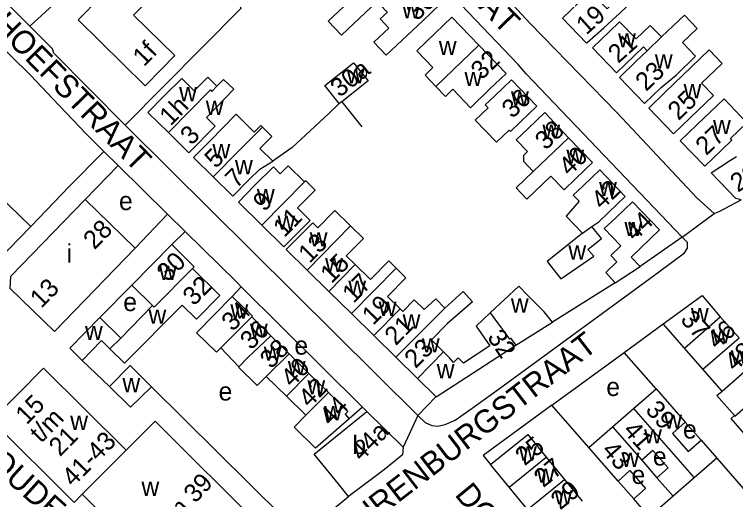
# Model space of a CAD drawing. Extents: x 161775 to 163181, y 382878 to 383925.
# Drawn here: x 162089.5 to 162245.9, y 383284.1 to 383389.4 of the extents above; entities that cross this region are included whole.
import ezdxf

# ---------------------------------------------------------------- set-up
doc = ezdxf.new("R2010")
doc.units = 0
for name, color, linetype in [('BLT_Basislijn', 7, 'Continuous'), ('BLT_Bebouwing', 7, 'Continuous'), ('BLT_Centroide', 7, 'Continuous'), ('BLT_Huisnummer', 7, 'Continuous'), ('BLT_Huisnummer_ tussenligend', 7, 'Continuous'), ('BLT_Huisnummer_reeks', 7, 'Continuous'), ('BLT_Onderverdeling_panden', 7, 'Continuous'), ('BLT_Straatnaam', 7, 'Continuous'), ('BLT_Vlakafsluiter', 7, 'Continuous')]:
    doc.layers.add(name, color=color, linetype=linetype)

msp = doc.modelspace()

# ---------------------------------------------------------------- linework, layer by layer
at = {"layer": 'BLT_Basislijn'}
for p, q in [((162092.87, 383386.85), (162105.88, 383398.85)), ((162160.52, 383370.45), (162164.88, 383365.03)), ((162101.31, 383351.92), (162108.95, 383359.68)), ((162112.07, 383356.6), (162108.95, 383359.68)), ((162112.07, 383356.6), (162104.91, 383349.23)), ((162122.75, 383346.08), (162112.07, 383356.6)), ((162115.77, 383338.71), (162122.75, 383346.08)), ((162126.57, 383342.32), (162122.75, 383346.08)), ((162123.66, 383339.48), (162126.57, 383342.32)), ((162234.37, 383341.1), (162225.23, 383334.73)), ((162108.07, 383323.63), (162115.01, 383330.69)), ((162219.85, 383331.17), (162206.25, 383322.64)), ((162136.8, 383328.2), (162138.75, 383330.31)), ((162221.8, 383316.06), (162230.27, 383322.28)), ((162206.1, 383304.59), (162221.8, 383316.06)), ((162228.69, 383308.2), (162221.8, 383316.06)), ((162104.22, 383314.35), (162110.16, 383308.68)), ((162119.27, 383308.6), (162151.77, 383276.48)), ((162177.06, 383302.39), (162180.93, 383306.42)), ((162165.07, 383304.18), (162166, 383303.24)), ((162214.1, 383295.44), (162206.1, 383304.59)), ((162238.47, 383297.02), (162235.04, 383300.94)), ((162223.85, 383284.29), (162220.45, 383288.17)), ((162151.77, 383276.48), (162162.02, 383284.83))]:
    msp.add_line(p, q, dxfattribs=at)
for points in [[(162125.25, 383476.9), (162123.02, 383475.95), (162121.82, 383474.13), (162121.64, 383471.58), (162122.43, 383469.75), (162125.33, 383466.48), (162163.61, 383428.2), (162170.77, 383419.99), (162181.31, 383409.13), (162201.49, 383387.36), (162220.16, 383368.12), (162237.6, 383349.53), (162241.27, 383346.24)], [(162234.37, 383341.1), (162200.53, 383376.54), (162198.79, 383378.55), (162180.32, 383397.96), (162171.16, 383407.28), (162152.54, 383427.04), (162145.46, 383434.09), (162144.51, 383435.3), (162141.14, 383438.66), (162128.28, 383452.45), (162114.65, 383465.76), (162108.97, 383469.83), (162104.5, 383472.05), (162097.57, 383474.16), (162097.57, 383474.32), (162092.85, 383474.91), (162089.56, 383474.77), (162025.83, 383467.96), (162025.67, 383467.75)], [(162114.43, 383407.55), (162118.99, 383411.97), (162119.75, 383411.23), (162136.39, 383393.66), (162138.37, 383391.5), (162138.68, 383390.7), (162113.58, 383365.34)], [(162092.87, 383386.85), (162075.69, 383403.95), (162072.1, 383408.19)], [(162036.52, 383357.08), (162059.8, 383379.79), (162066.65, 383386.36), (162068.12, 383387.55), (162074.17, 383393.72), (162075.21, 383393.82), (162093.13, 383376.16), (162097.9, 383371.1)], [(162113.58, 383365.34), (162098.09, 383380.96), (162097.78, 383381.95), (162093.25, 383386.47), (162092.87, 383386.85)], [(162108.95, 383359.68), (162105.09, 383363.48), (162097.9, 383371.1)], [(162160.01, 383370.04), (162157.65, 383367.84), (162149.81, 383360.51), (162145.58, 383357.59)], [(162113.58, 383365.34), (162113.98, 383364.93), (162177.06, 383302.39)], [(162093.09, 383343.41), (162099.88, 383350.45), (162101.31, 383351.92)], [(162241.27, 383346.24), (162242.36, 383346.62), (162247.15, 383349.17)], [(162138.75, 383330.31), (162137.68, 383331.37), (162126.57, 383342.32)], [(162177.06, 383302.39), (162178.64, 383300.88), (162180.1, 383300.19), (162181.38, 383300.08), (162182.96, 383300.43), (162185.1, 383301.34), (162189.29, 383304.3), (162194.72, 383308.27), (162223.02, 383328.96), (162229.49, 383333.71), (162234.9, 383337.68), (162235.51, 383338.68), (162235.51, 383339.94), (162234.37, 383341.1)], [(162138.75, 383330.31), (162165.07, 383304.18)], [(162165.07, 383304.18), (162162.15, 383301.66)], [(162206.1, 383304.59), (162191.24, 383293.73), (162192.82, 383291.78)], [(162241.86, 383293.15), (162278.02, 383251.56)]]:
    msp.add_lwpolyline(points, dxfattribs=at)
at = {"layer": 'BLT_Bebouwing'}
for p, q in [((162214.91, 383382.14), (162220.11, 383376.72)), ((162160.52, 383370.45), (162160.01, 383370.04)), ((162227.11, 383369.06), (162232.46, 383363.48)), ((162233.96, 383361.97), (162239.26, 383356.45)), ((162081.91, 383354.21), (162093.09, 383343.41)), ((162104.91, 383349.23), (162115.77, 383338.71)), ((162093.09, 383343.41), (162085.05, 383335.1)), ((162214.8, 383343.37), (162216.26, 383344.39)), ((162115.77, 383338.71), (162098.23, 383320.61)), ((162123.66, 383339.48), (162115.01, 383330.69)), ((162153.02, 383333.95), (162157.75, 383329.3)), ((162219.85, 383331.17), (162225.23, 383334.73)), ((162115.01, 383330.69), (162119.51, 383326.24)), ((162157.75, 383329.3), (162162.65, 383324.49)), ((162129.05, 383320.35), (162136.8, 383328.2)), ((162119.51, 383326.24), (162112.59, 383319.19)), ((162162.65, 383324.49), (162167.52, 383319.71)), ((162112.59, 383319.19), (162108.07, 383323.63)), ((162141.01, 383323.76), (162145.13, 383319.7)), ((162198.29, 383317.65), (162206.25, 383322.64)), ((162145.13, 383319.7), (162149.11, 383315.78)), ((162167.52, 383319.71), (162172.3, 383315.02)), ((162138.25, 383312.96), (162134.3, 383317.03)), ((162149.11, 383315.78), (162153.43, 383311.52)), ((162172.3, 383315.02), (162176.96, 383310.44)), ((162148.54, 383306.55), (162144.15, 383310.88)), ((162153.43, 383311.52), (162157.63, 383307.38)), ((162228.69, 383308.2), (162235.04, 383300.94)), ((162152.73, 383302.42), (162148.54, 383306.55)), ((162192.82, 383291.78), (162200.92, 383298.24)), ((162200.92, 383298.24), (162204.89, 383293.35)), ((162238.47, 383297.02), (162241.86, 383293.15)), ((162220.45, 383288.17), (162214.1, 383295.44)), ((162204.89, 383293.35), (162208.83, 383288.49)), ((162196.86, 383286.82), (162192.82, 383291.78)), ((162225.58, 383292.66), (162228.88, 383288.89)), ((162208.83, 383288.49), (162212.67, 383283.77)), ((162200.8, 383281.97), (162196.86, 383286.82)), ((162227.26, 383280.38), (162223.85, 383284.29))]:
    msp.add_line(p, q, dxfattribs=at)
for points in [[(162121.43, 383377.49), (162117.92, 383373.92), (162103.35, 383388.24), (162108.24, 383393.22), (162107.37, 383394.08), (162110.9, 383397.66), (162114.39, 383401.21), (162115.42, 383400.2), (162120.29, 383405.15), (162126.89, 383398.67), (162121.51, 383393.18), (162120.38, 383394.3), (162115.4, 383389.24), (162124.34, 383380.46), (162121.43, 383377.49)], [(162176.95, 383396.62), (162172.09, 383401.7), (162168.48, 383398.24), (162157.57, 383387.97), (162160.49, 383384.91), (162168.2, 383392.17), (162170.15, 383390.12)], [(162213.78, 383383.32), (162217.34, 383386.51), (162220.95, 383389.74), (162227.56, 383396.09), (162224.76, 383399), (162218.76, 383393.24), (162219.75, 383392.2), (162218.08, 383390.6), (162214.46, 383394.37), (162212.03, 383392.04), (162208.42, 383388.58)], [(162170.15, 383390.12), (162170.41, 383389.84), (162168.89, 383388.41), (162170.72, 383386.44), (162167.47, 383383.37), (162170.18, 383380.53), (162178.2, 383388.09), (162181.81, 383391.54), (162176.95, 383396.62)], [(162190.27, 383382.7), (162184.38, 383388.79), (162180.77, 383385.34), (162176.8, 383381.53), (162180.32, 383377.86), (162178.6, 383376.22), (162180.94, 383373.78)], [(162208.42, 383388.58), (162213.61, 383383.17), (162213.78, 383383.32)], [(162226.17, 383370.05), (162229.79, 383373.52), (162233.15, 383376.32), (162237.27, 383380.31), (162234.42, 383383.34), (162237.59, 383386.32), (162234.85, 383389.24), (162231.19, 383385.8), (162229.86, 383384.51)], [(162229.86, 383384.51), (162227.43, 383387.03), (162224.36, 383384.08), (162220.8, 383387.8), (162218.51, 383385.6), (162214.91, 383382.14)], [(162180.94, 383373.78), (162183.02, 383371.61), (162184.64, 383373.16), (162188.49, 383369.15), (162192.49, 383373.1), (162196.18, 383376.57), (162190.27, 383382.7)], [(162220.11, 383376.72), (162226.01, 383382.37), (162226.75, 383381.49)], [(162226.75, 383381.49), (162224.35, 383379.18), (162220.91, 383375.88)], [(162232.46, 383363.48), (162236.07, 383366.95), (162241.18, 383371.78), (162238.57, 383374.5), (162243.02, 383378.77), (162240.22, 383381.68), (162230.71, 383372.53), (162227.11, 383369.06)], [(162160.01, 383370.04), (162156.88, 383373.99), (162163.1, 383378.92), (162166.23, 383374.98), (162160.52, 383370.45)], [(162133.46, 383373.82), (162131.46, 383375.79), (162128.54, 383372.84), (162125.83, 383375.51), (162122.01, 383371.71), (162118.49, 383368.15), (162122.93, 383363.77)], [(162122.93, 383363.77), (162127.36, 383359.4), (162133.07, 383365.19), (162131.19, 383367.01), (162137.14, 383373.19), (162134.88, 383375.26), (162133.46, 383373.82)], [(162197.14, 383364.02), (162199.24, 383366.01), (162202.85, 383369.47), (162197.34, 383375.23), (162193.73, 383371.77), (162191.63, 383369.79), (162192.26, 383369.11), (162189.5, 383366.47), (162194.12, 383361.65), (162196.88, 383364.29), (162197.14, 383364.02)], [(162220.91, 383375.88), (162220.74, 383375.72), (162226.17, 383370.05)], [(162239.26, 383356.45), (162242.87, 383359.92), (162245.17, 383362.12), (162244.85, 383362.45), (162248.42, 383365.88), (162243.44, 383371.07), (162237.57, 383365.43), (162233.96, 383361.97)], [(162209.74, 383362.66), (162204.55, 383368.09), (162200.94, 383364.63), (162198.38, 383362.18), (162200.82, 383359.63), (162199.94, 383358.79), (162199.93, 383357.53), (162202.05, 383355.31)], [(162143.33, 383364.96), (162142.98, 383365.3), (162141.56, 383363.86), (162137.61, 383367.76), (162131.9, 383361.91), (162128.38, 383358.35), (162132.65, 383354.15)], [(162145.58, 383357.59), (162142.8, 383360.33), (162145.38, 383362.93), (162143.33, 383364.96)], [(162202.05, 383355.31), (162198.35, 383351.75), (162200.68, 383349.32), (162205.9, 383354.32), (162208.76, 383351.33), (162211.32, 383353.78), (162214.93, 383357.24), (162209.74, 383362.66)], [(162132.65, 383354.15), (162136.91, 383349.94), (162140.42, 383353.5), (162142.74, 383355.8), (162145.58, 383357.59)], [(162240.63, 383355.05), (162244.84, 383357.75), (162246.15, 383358.59)], [(162152.48, 383353.06), (162148.93, 383356.57), (162147.21, 383354.83), (162145.72, 383356.31), (162141.65, 383352.26), (162138.14, 383348.7), (162143.23, 383343.68)], [(162216.26, 383344.39), (162218.41, 383346.44), (162222.02, 383349.9), (162216.51, 383355.66), (162212.89, 383352.2), (162210.75, 383350.15), (162211.99, 383348.86), (162209.17, 383345.61), (162212.77, 383341.95)], [(162247.15, 383349.17), (162245.99, 383349.43), (162240.63, 383355.05)], [(162143.23, 383343.68), (162147.99, 383338.98), (162151.5, 383342.54), (162153.71, 383344.72), (162150.97, 383347.42), (162154.8, 383351.3), (162152.75, 383353.33), (162152.48, 383353.06)], [(162098.23, 383320.61), (162088.59, 383329.95), (162088.78, 383332.59), (162104.91, 383349.23)], [(162219.96, 383345.3), (162223.57, 383348.76), (162229.42, 383342.65), (162223.28, 383336.77), (162225.23, 383334.73)], [(162162.43, 383343.53), (162159.07, 383346.85), (162155.38, 383343.11), (162154.29, 383344.18), (162152, 383341.96), (162148.49, 383338.4), (162153.02, 383333.95)], [(162219.85, 383331.17), (162217.82, 383333.43), (162220.21, 383335.74), (162218.9, 383337.12), (162221.05, 383339.18), (162217.47, 383342.92), (162219.96, 383345.3)], [(162162.43, 383343.53), (162165.22, 383340.78), (162161.53, 383337.04), (162163.47, 383335.12)], [(162212.77, 383341.95), (162205.06, 383335.82), (162208.07, 383332.05), (162215.22, 383336.94), (162213.87, 383338.41), (162216.89, 383340.82), (162214.8, 383343.37)], [(162128.16, 383334.28), (162128.52, 383334.65), (162123.66, 383339.48)], [(162163.47, 383335.12), (162166.75, 383331.89), (162170.72, 383335.91), (162172.32, 383334.34)], [(162110.27, 383316.82), (162113.42, 383313.71), (162125.92, 383326.35), (162129.01, 383323.28), (162134.09, 383328.42), (162128.16, 383334.28)], [(162172.32, 383334.34), (162174.45, 383332.23), (162170.48, 383328.2), (162173.21, 383325.51)], [(162182.87, 383325.64), (162186.87, 383329.31), (162188.9, 383327.07), (162183.5, 383322.34), (162180.01, 383318.8), (162182.63, 383316.21)], [(162206.25, 383322.64), (162204.44, 383324.88), (162200.92, 383328.43), (162198.91, 383330.47), (162192.74, 383324.64)], [(162136.8, 383328.2), (162141.15, 383323.9), (162141.01, 383323.76)], [(162173.21, 383325.51), (162173.76, 383324.97), (162176.25, 383327.5), (162178.41, 383325.37), (162180.97, 383327.71), (162182.87, 383325.64)], [(162230.27, 383322.28), (162238.67, 383328.4), (162242.64, 383323.81)], [(162192.74, 383324.64), (162189.7, 383321.76), (162192.66, 383317.49), (162186.91, 383313.77), (162185.76, 383314.91), (162184.78, 383313.91), (162183.94, 383314.93), (162182.63, 383316.21)], [(162108.07, 383323.63), (162101.53, 383317.02), (162104.22, 383314.35)], [(162242.64, 383323.81), (162246.69, 383319.24)], [(162234.87, 383317.02), (162230.27, 383322.28)], [(162134.3, 383317.03), (162133.35, 383316.11), (162129.05, 383320.35)], [(162104.22, 383314.35), (162108.45, 383318.63), (162110.27, 383316.82)], [(162176.96, 383310.44), (162181.01, 383306.46), (162198.29, 383317.65)], [(162238.88, 383312.42), (162234.87, 383317.02)], [(162113.79, 383294.87), (162095.85, 383312.66), (162084.57, 383301.31), (162102.48, 383283.52), (162104.26, 383285.33)], [(162119.27, 383308.6), (162114.63, 383313.21), (162110.16, 383308.68)], [(162144.15, 383310.88), (162142.18, 383308.89), (162138.15, 383312.86), (162138.25, 383312.96)], [(162243.03, 383307.68), (162238.88, 383312.42)], [(162110.16, 383308.68), (162114.69, 383304.21), (162119.27, 383308.6)], [(162157.63, 383307.38), (162161.82, 383303.24), (162161.27, 383302.68), (162162.15, 383301.66)], [(162223.78, 383303.9), (162228.69, 383308.2)], [(162245.71, 383302.36), (162241.89, 383306.72), (162243.03, 383307.68)], [(162154.83, 383295.33), (162150.22, 383299.87), (162152.73, 383302.42)], [(162162.02, 383284.83), (162159.76, 383287.61), (162154.59, 383293.97), (162166, 383303.24)], [(162166, 383303.24), (162173.86, 383295.54)], [(162219.24, 383299.92), (162223.78, 383303.9)], [(162104.26, 383285.33), (162108.15, 383281.44), (162106.4, 383279.68), (162108.41, 383277.67), (162125.62, 383260.44), (162143.21, 383278.05), (162120.07, 383301.15), (162113.79, 383294.87)], [(162162.15, 383301.66), (162154.83, 383295.33)], [(162235.04, 383300.94), (162232.26, 383298.51), (162235.68, 383294.59), (162238.47, 383297.02)], [(162251.05, 383294.75), (162244.97, 383301.71), (162245.71, 383302.36)], [(162214.1, 383295.44), (162219.24, 383299.92)], [(162173.86, 383295.54), (162173.69, 383293.84), (162169.81, 383290.68), (162162.02, 383284.83)], [(162228.88, 383288.89), (162231.31, 383291.02), (162228.01, 383294.79), (162225.58, 383292.66)], [(162241.86, 383293.15), (162236.94, 383288.85)], [(162220.45, 383288.17), (162223.02, 383290.42), (162226.42, 383286.54), (162223.85, 383284.29)], [(162236.94, 383288.85), (162232.4, 383284.87)], [(162232.4, 383284.87), (162227.26, 383280.38)]]:
    msp.add_lwpolyline(points, dxfattribs=at)
at = {"layer": 'BLT_Onderverdeling_panden'}
for p, q in [((162226.75, 383381.49), (162229.86, 383384.51)), ((162180.94, 383373.78), (162190.27, 383382.7)), ((162209.74, 383362.66), (162202.05, 383355.31)), ((162143.23, 383343.68), (162152.48, 383353.06)), ((162153.02, 383333.95), (162162.43, 383343.53)), ((162212.77, 383341.95), (162214.8, 383343.37)), ((162157.75, 383329.3), (162163.47, 383335.12)), ((162162.65, 383324.49), (162172.32, 383334.34)), ((162167.52, 383319.71), (162173.21, 383325.51)), ((162172.3, 383315.02), (162182.87, 383325.64)), ((162141.01, 383323.76), (162134.3, 383317.03)), ((162234.87, 383317.02), (162242.64, 383323.81)), ((162110.27, 383316.82), (162112.59, 383319.19)), ((162238.88, 383312.42), (162246.69, 383319.24)), ((162149.11, 383315.78), (162144.15, 383310.88)), ((162182.63, 383316.21), (162176.96, 383310.44)), ((162153.43, 383311.52), (162148.54, 383306.55)), ((162157.63, 383307.38), (162152.73, 383302.42)), ((162223.78, 383303.9), (162236.94, 383288.85)), ((162219.24, 383299.92), (162225.58, 383292.66)), ((162113.79, 383294.87), (162104.26, 383285.33)), ((162196.86, 383286.82), (162204.89, 383293.35)), ((162200.8, 383281.97), (162208.83, 383288.49)), ((162228.88, 383288.89), (162232.4, 383284.87))]:
    msp.add_line(p, q, dxfattribs=at)
for points in [[(162122.93, 383363.77), (162132.05, 383373.01), (162132.36, 383372.71), (162133.46, 383373.82)], [(162132.65, 383354.15), (162138.46, 383360.03), (162143.33, 383364.96)], [(162119.51, 383326.24), (162119.84, 383325.92), (162128.16, 383334.28)], [(162192.74, 383324.64), (162196.92, 383318.98), (162197.14, 383319.16), (162198.29, 383317.65)], [(162145.13, 383319.7), (162140.12, 383314.86), (162138.25, 383312.96)], [(162243.03, 383307.68), (162249.7, 383313.51)], [(162245.71, 383302.36), (162245.79, 383302.26), (162253.58, 383309.08)]]:
    msp.add_lwpolyline(points, dxfattribs=at)
at = {"layer": 'BLT_Vlakafsluiter'}
for p, q in [((162234.37, 383341.1), (162241.27, 383346.24)), ((162177.06, 383302.39), (162173.86, 383295.54))]:
    msp.add_line(p, q, dxfattribs=at)

# ---------------------------------------------------------------- texts
at = {"layer": 'BLT_Centroide'}
for s, p in [('w', (162173.66, 383388.56)), ('w', (162220.46, 383382.25)), ('w', (162181.59, 383380.59)), ('w', (162228.44, 383377.66)), ('w', (162161.6, 383374.44)), ('w', (162187.15, 383373.86)), ('w', (162125.27, 383370.55)), ('w', (162234.67, 383371.22)), ('w', (162197.24, 383369.62)), ('w', (162131.05, 383367.58)), ('w', (162241.05, 383363.45)), ('w', (162204.05, 383362.44)), ('w', (162132.49, 383358.2)), ('w', (162209.25, 383357)), ('w', (162137.38, 383354.71)), ('w', (162216.34, 383349.98)), ('w', (162142.13, 383348.43)), ('e', (162112.23, 383346.95)), ('w', (162146.59, 383342.7)), ('w', (162221.84, 383341.31)), ('w', (162153.59, 383339.06)), ('i', (162100.85, 383335.55)), ('w', (162209.68, 383336.21)), ('w', (162156.92, 383333.49)), ('w', (162120.91, 383331.81)), ('w', (162161.95, 383328.6)), ('e', (162113.16, 383325.03)), ('w', (162197.21, 383324.72)), ('w', (162136.39, 383323.42)), ('w', (162168.55, 383324)), ('w', (162118.62, 383322.29)), ('w', (162173.73, 383321.25)), ('w', (162236.26, 383322.62)), ('w', (162104.85, 383318.76)), ('w', (162140.62, 383319.25)), ('w', (162240.91, 383318.03)), ('e', (162150.27, 383315.59)), ('w', (162177.91, 383316.06)), ('w', (162143.62, 383314.28)), ('w', (162244.93, 383313.44)), ('w', (162148.83, 383311.17)), ('w', (162181.13, 383310.45)), ('w', (162112.97, 383307.43)), ('e', (162133.83, 383305.63)), ('w', (162153.08, 383306.97)), ('e', (162217.91, 383306.61)), ('w', (162156.74, 383301.34)), ('w', (162230.48, 383299.51)), ('w', (162101.65, 383299.24)), ('w', (162226.11, 383296.31)), ('e', (162234.55, 383297.39)), ('b', (162162.85, 383294.03)), ('w', (162198.96, 383292.59)), ('e', (162228.02, 383291.53)), ('w', (162221.21, 383291.22)), ('w', (162202.83, 383287.81)), ('e', (162223.38, 383287.53)), ('w', (162117.1, 383284.95)), ('w', (162206.67, 383283.09))]:
    msp.add_text(s, height=4, dxfattribs=at).set_placement(p)
at = {"layer": 'BLT_Huisnummer'}
for s, rotation, p in [('30', 43.7356, (162176.86, 383387.82)), ('19', 41.8467, (162213.59, 383384.82)), ('1f', 45.5023, (162117.64, 383377.91)), ('21', 41.8467, (162220.5, 383378.64)), ('32', 43.8348, (162190.86, 383375.03)), ('30a', 38.6116, (162160.09, 383371.26)), ('23', 43.8252, (162226.54, 383372.54)), ('36', 43.7439, (162197.56, 383366.66)), ('25', 43.8252, (162233.58, 383366.25)), ('1h', 45.3736, (162123.42, 383365.03)), ('3', 45.3727, (162127.94, 383360.84)), ('38', 43.7439, (162204.78, 383359.79)), ('27', 43.8332, (162239.59, 383358.62)), ('5', 45.3727, (162133.22, 383355.81)), ('40', 43.7439, (162209.92, 383354.16)), ('7', 45.3889, (162137.68, 383351.48)), ('29', 32.6471, (162246.44, 383350.7)), ('42', 43.7439, (162216.97, 383346.87)), ('9', 45.3889, (162143.72, 383346.45)), ('11', 45.3727, (162148.08, 383340.85)), ('44', 43.7367, (162224.11, 383340.05)), ('13', 45.3727, (162153.55, 383335.24)), ('30', 45.4014, (162122.83, 383331.19)), ('32', 45.4014, (162128.48, 383325.99)), ('17', 45.5216, (162163.09, 383326.56)), ('34', 45.4014, (162136.89, 383320.46)), ('37', 311.1671, (162233.8, 383323.07)), ('21', 45.5198, (162172.26, 383317.4)), ('46', 41.1671, (162241.87, 383316.52)), ('32', 303.3956, (162191.97, 383319.38)), ('38', 45.4068, (162145.22, 383312.33)), ('23', 45.3905, (162176.55, 383312.42)), ('48', 41.1671, (162245.74, 383311.75)), ('42', 45.4013, (162153.55, 383303.9)), ('44', 45.4013, (162158.1, 383299.93)), ('39', 311.1678, (162226.21, 383303.48)), ('44a', 45.4013, (162164.82, 383292.26)), ('25', 39.0628, (162200.2, 383291.33)), ('43', 311.1678, (162216.72, 383294.69)), ('27', 39.0628, (162204.25, 383286.61))]:
    msp.add_text(s, height=4, rotation=rotation, dxfattribs=at).set_placement(p)
at = {"layer": 'BLT_Huisnummer_ tussenligend'}
for s, rotation, p in [('15', 45.5216, (162158.33, 383330.85)), ('19', 45.5198, (162167.36, 383321.81)), ('36', 45.4014, (162140.91, 383316.43)), ('40', 45.4068, (162149.74, 383308.3)), ('41', 311.1678, (162221.36, 383299.02)), ('29', 39.0628, (162207.9, 383281.75))]:
    msp.add_text(s, height=4, rotation=rotation, dxfattribs=at).set_placement(p)
at = {"layer": 'BLT_Huisnummer_reeks'}
for s, rotation, p in [('28', 45.4014, (162106.9, 383338.21)), ('13', 45.4014, (162095.36, 383325.48)), ('15', 45.4014, (162092.22, 383300.23)), ('t/m', 45.4014, (162095.32, 383296.25)), ('21', 45.4014, (162099.45, 383293.32)), ('41-43', 45.4014, (162102.27, 383286.76)), ('23 t/m 39', 47.0641, (162117.64, 383271.23))]:
    msp.add_text(s, height=4, rotation=rotation, dxfattribs=at).set_placement(p)
at = {"layer": 'BLT_Straatnaam'}
for s, rotation, p in [('LAKERSTRAAT', 314.2234, (162162.3, 383419.44)), ('DOMMELHOEFSTRAAT', 314.5461, (162063.96, 383407.85)), ('TREURENBURGSTRAAT', 37.6265, (162154.49, 383269.26)), ('GASHOUDER', 318.0001, (162069.45, 383304.59)), ('DOMMELHOEFSTRAAT', 309.5461, (162184.87, 383285.16))]:
    msp.add_text(s, height=5, rotation=rotation, dxfattribs=at).set_placement(p)

doc.saveas('drawing.dxf')
